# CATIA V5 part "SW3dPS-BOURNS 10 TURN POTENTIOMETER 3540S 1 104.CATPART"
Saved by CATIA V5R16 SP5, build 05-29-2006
Part number: F3C2AC45-4847-49BC-8D47-41633D3B7B72
Revision: ANY
Definition: F3C2AC45-4847-49BC-8D47-41633D3B7B72
Source: Unknown
Bounding box of the stored display mesh (mm): x -11.113 to 11.113, y -10.944 to 16.269, z 0 to 39.922
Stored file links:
  C:\Documents and Settings\Proprietário\Ambiente de trabalho\Coluna\SuportePotenciometro\potenciometro\SW3dPS-BOURNS 10 TURN POTENTIOMETER 3540S 1 104.CATPART
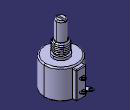
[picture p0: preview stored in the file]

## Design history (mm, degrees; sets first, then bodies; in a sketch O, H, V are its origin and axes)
Set1
  DatumCurve1
  DatumCurve2
Body1 "NONE" (main body)
  Solid1 "Manifold Solid #166": solid without history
